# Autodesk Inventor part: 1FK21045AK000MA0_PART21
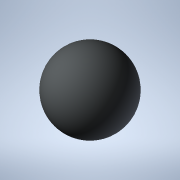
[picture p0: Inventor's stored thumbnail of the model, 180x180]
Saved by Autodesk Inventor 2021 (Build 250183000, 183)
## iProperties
Created: 2025-04
Part Number: 1FK21045AK000MA0_PART21
Material: Generic
Catalog Web Link: www.3dfindit.com
Description: -Servo synchronous motor
Document SubType Name: Modeling
Designer: psAdmin
Mass: 0.137258 g
Surface Area: 1.2868 cm^2
Volume: 0.137258 cm^3
Density: 1 g/cm^3
Appearance: PSOLRGB-212-217-219
Category: PARTsolutions
Title: 1FK21045AK000MA0_PART21
Author: Cadenas PARTsolutions
Comments: Servo synchronous motor
Sending System: PARTsolutions
Preprocessor: ST-DEVELOPER v19.3
PSOL_IDENT_0: {$CADENAS_DATA/23d-libs/siemens_ag/_cat_/3d/2f/1fk21045ak000ma0.prj},216 {VTYP=3D},{NB=1FK21045AK000
PSOL_IDENT_1: MA0_PART21},{LINA=1FK21045AK000MA0_PART21},{NN=1FK21045AK000MA0_PART21},{NOPRJ=TRUE},{DATE=19.08.202
PSOL_IDENT_2: 5 14:00:34},{GEOMDATE=30.07.2025 02:01:24},{VERSION=},{LINEID=10},{WBVAR=},{WBNUMERIC=}  {NB=1FK2104
PSOL_IDENT_3: 5AK000MA0_PART21},{LINA=1FK21045AK000MA0_PART21},{KT=DUMMY},{PREVIEW=../../../_pool_/a9/69/p_d211_xx
PSOL_IDENT_4: _00818j.png},{DESCSHORT=SIMOTICS S-1FK2 HD, SINAMICS S210 3AC 400V-480V, 1.7 Nm, 6000 rpm},{DESCLONG=
PSOL_IDENT_5: SIMOTICS S-1FK2 HD servo motor M0=2.4 Nm; PN = 1.07 kW at nN=6000 rpm (380-480 V); PN = 0.75 kW at n
PSOL_IDENT_6: N=3000 rpm (200-240 V); degree of protection IP64; cylindrical shaft D19x40mm; absolute encoder 22-b
PSOL_IDENT_7: it + 12-bit multiturn (encoder AM22DQC); with OCC interface; plug size M17, rotatable; SIMOTICS S-1F
PSOL_IDENT_8: K2 servomotorfor a wide range of uses in industrial environments. SIMOTICS S‑1FK2 servomotors are co
PSOL_IDENT_9: mpact synchronous motors with a high dynamic performance that set themselves apart as a result of th
PSOL_IDENT_10: eir high power density, degree of protection and overload capability. The motors are available in tw
PSOL_IDENT_11: o variants: as High Dynamic variant (highest dynamic performance as a result of the low intrinsic mo
PSOL_IDENT_12: ment of inertia for applications demanding a high dynamic performance with low moved masses) - and a
PSOL_IDENT_13: s Compact variant (precise and stable closed-loop control for medium up to large moved masses as a r
PSOL_IDENT_14: esult of a medium intrinsic moment of inertia). SIMOTICSS‑1FK2 servomotors fully exploit their stren
PSOL_IDENT_15: gths in a system with the SINAMICSS210 frequency converter and simple connection using the one cable
PSOL_IDENT_16: connection (OCC). Advantages include the short control and positioning times, fast and precise corr
PSOL_IDENT_17: ection of disturbing quantities as well as stable control with a high dynamic performance. The servo
PSOL_IDENT_18: motors can be configured to address a wide range of requirements. For example with and without hold
PSOL_IDENT_19: ing brake, IP64 or IP65 degree of protection, singleturn or multiturn absolute encoders - to name ju
PSOL_IDENT_20: st a few. Further, the servomotors are available in different shaft heights extending from 20 to 100
PSOL_IDENT_21: . A shaft sealing ring is available to achieve an IP65 degree of protection and for subsequent mount
PSOL_IDENT_22: ing at the motor or as spare part. SIMOTICS - the optimum motor for each and every motion control ap
PSOL_IDENT_23: plication.},{INTNO=804766789342},{SUPPLIERALTNO=1FK2104-5AK00-0MA0},{MANUID=1FK21045AK000MA0},{MANUN
PSOL_IDENT_24: AME=Siemens},{MANUTYPEDESC=Synchronous motor 1FK2-HD 2,39 Nm},{AAU732=SIMOTICS},{AAO057=S-1FK2},{AAU
PSOL_IDENT_25: 734=SIMOTICS S-1FK2 HD servo motor M0=2.4 Nm; PN = 1.07 kW at nN=6000 rpm (380-480 V); PN = 0.75 kW
PSOL_IDENT_26: at nN=3000 rpm (200-240 V); degree of protection IP64; cylindrical shaft D19x40mm; absolute encoder
PSOL_IDENT_27: 22-bit + 12-bit multiturn (encoder AM22DQC); with OCC interface; plug size M17, rotatable;},{AAW338=
PSOL_IDENT_28: Synchronous motor 1FK2-HD 2,39 Nm},{AAO742=SIMOTICS},{AAO663=4042948691151},{NOCUPEROU=1},{PRICEQUAN
PSOL_IDENT_29: TITY=1},{QUANTITYMIN=1},{QUANTITYINT=1},{CTN=85015100},{COO=DE},{AAO676=1FK2104-5AK00-0MA0},{AAO677=
PSOL_IDENT_30: Siemens AG},{ORDERUNIT=C62},{CONTENTUNIT=C62}
NB: 1FK21045AK000MA0_PART21
NT: Servo synchronous motor
NBSYN: $MANUID._PART21
LINA: 1FK21045AK000MA0_PART21
CATALOG: SIEMENS
PREVIEW: ../../../_pool_/a9/69/p_d211_xx_00818j.png
DESCSHORT: SIMOTICS S-1FK2 HD, SINAMICS S210 3AC 400V-480V, 1.7 Nm, 6000 rpm
DESCLONG: SIMOTICS S-1FK2 HD servo motor M0=2.4 Nm; PN = 1.07 kW at nN=6000 rpm (380-480 V); PN = 0.75 kW at nN=3000 rpm (200-240 V); degree of protection IP64; cylindric
INTNO: 804766789342
SUPPLIERALTNO: 1FK2104-5AK00-0MA0
MANUID: 1FK21045AK000MA0
MANUNAME: Siemens
MANUTYPEDESC: Synchronous motor 1FK2-HD 2,39 Nm
AAU732: SIMOTICS
AAO057: S-1FK2
AAU734: SIMOTICS S-1FK2 HD servo motor M0=2.4 Nm; PN = 1.07 kW at nN=6000 rpm (380-480 V); PN = 0.75 kW at nN=3000 rpm (200-240 V); degree of protection IP64; cylindric
AAW338: Synchronous motor 1FK2-HD 2,39 Nm
AAO742: SIMOTICS
AAO663: 4042948691151.0
NOCUPEROU: 1
PRICEQUANTITY: 1
QUANTITYMIN: 1
QUANTITYINT: 1
CTN: 85015100
COO: DE
ARTICLENO: 1FK21045AK000MA0_PART21
BOMINFO: 1FK21045AK000MA0_PART21
CREATOR: CADENAS GmbH
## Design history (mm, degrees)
feature "2025_04_17_15_39_51_0728"
body "Solid1"
